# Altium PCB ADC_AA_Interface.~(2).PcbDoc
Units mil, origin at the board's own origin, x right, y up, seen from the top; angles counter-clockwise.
Board outline 2600 x 10000 mil, 6 copper layers (Top Layer, InternalPlane1, MidLayer1, InternalPlane2, InternalPlane3, Bottom Layer); 10 components, 66 nets, 279 pads, 13 vias.
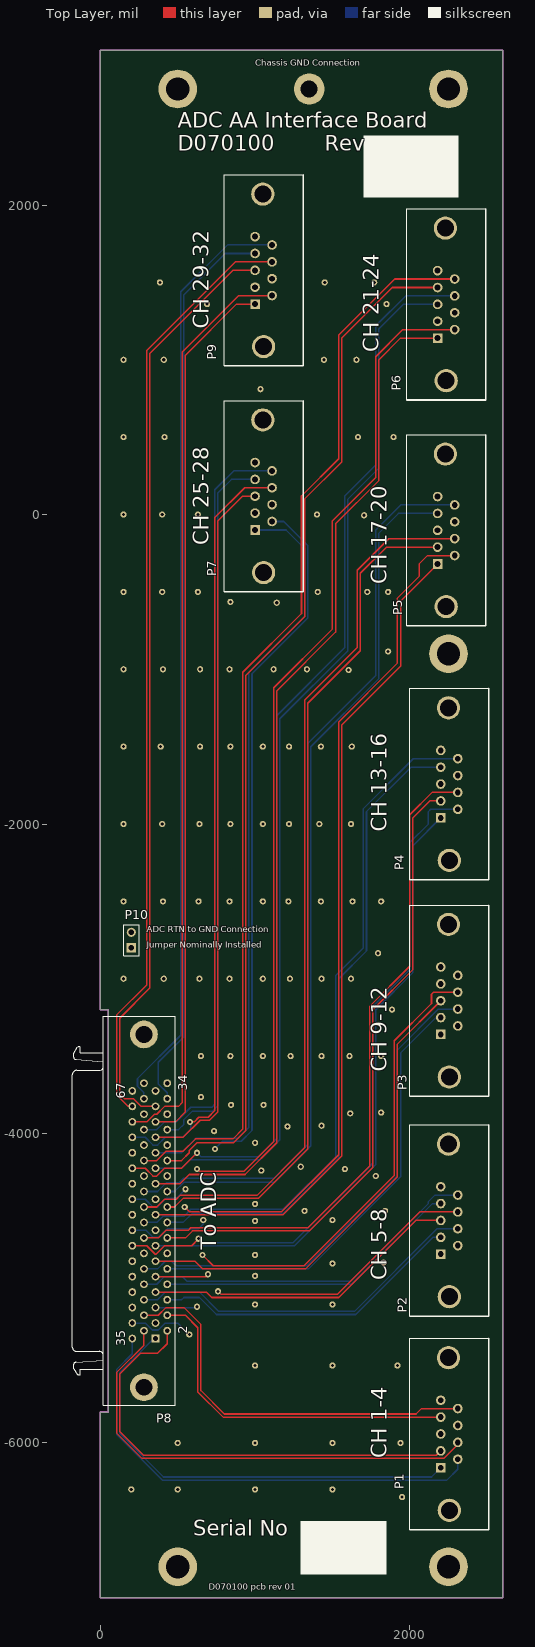
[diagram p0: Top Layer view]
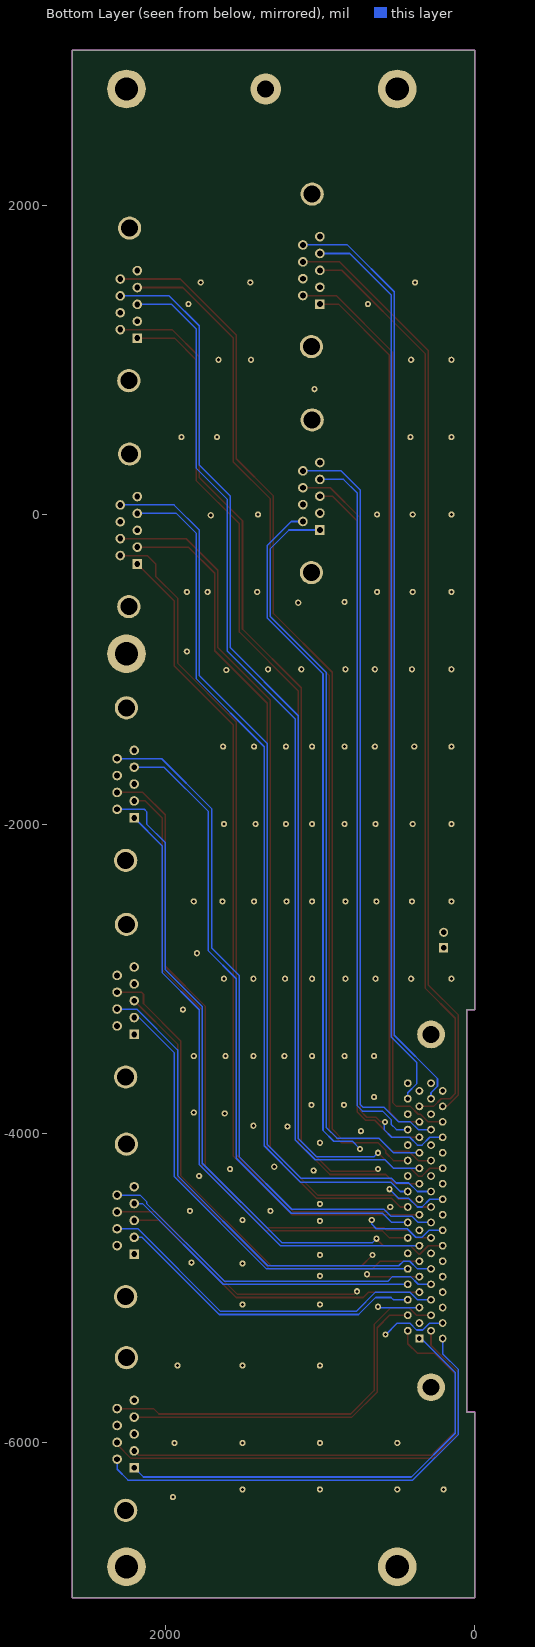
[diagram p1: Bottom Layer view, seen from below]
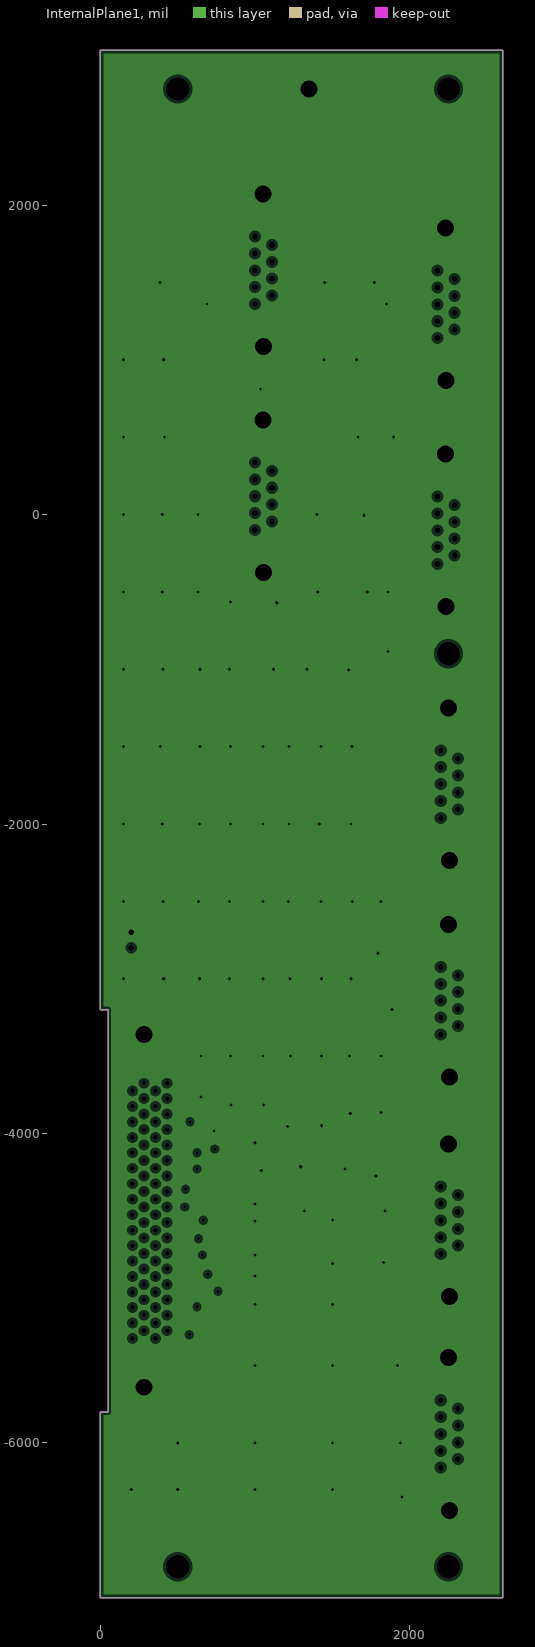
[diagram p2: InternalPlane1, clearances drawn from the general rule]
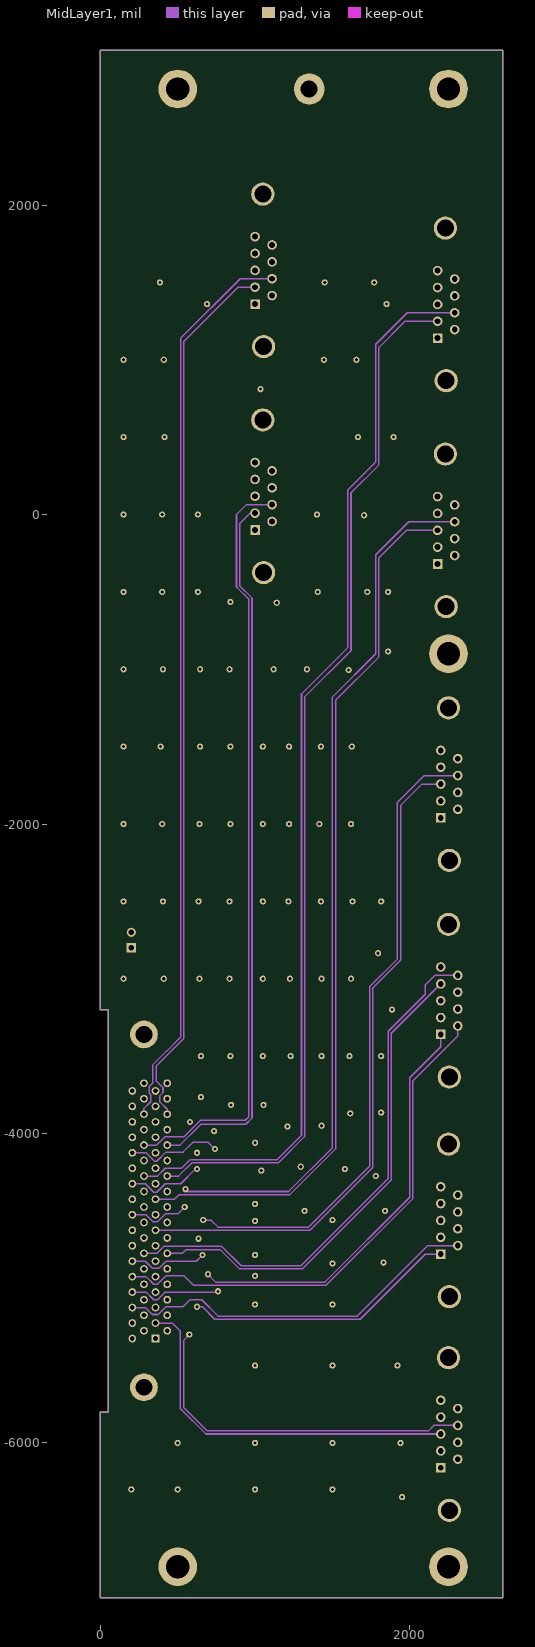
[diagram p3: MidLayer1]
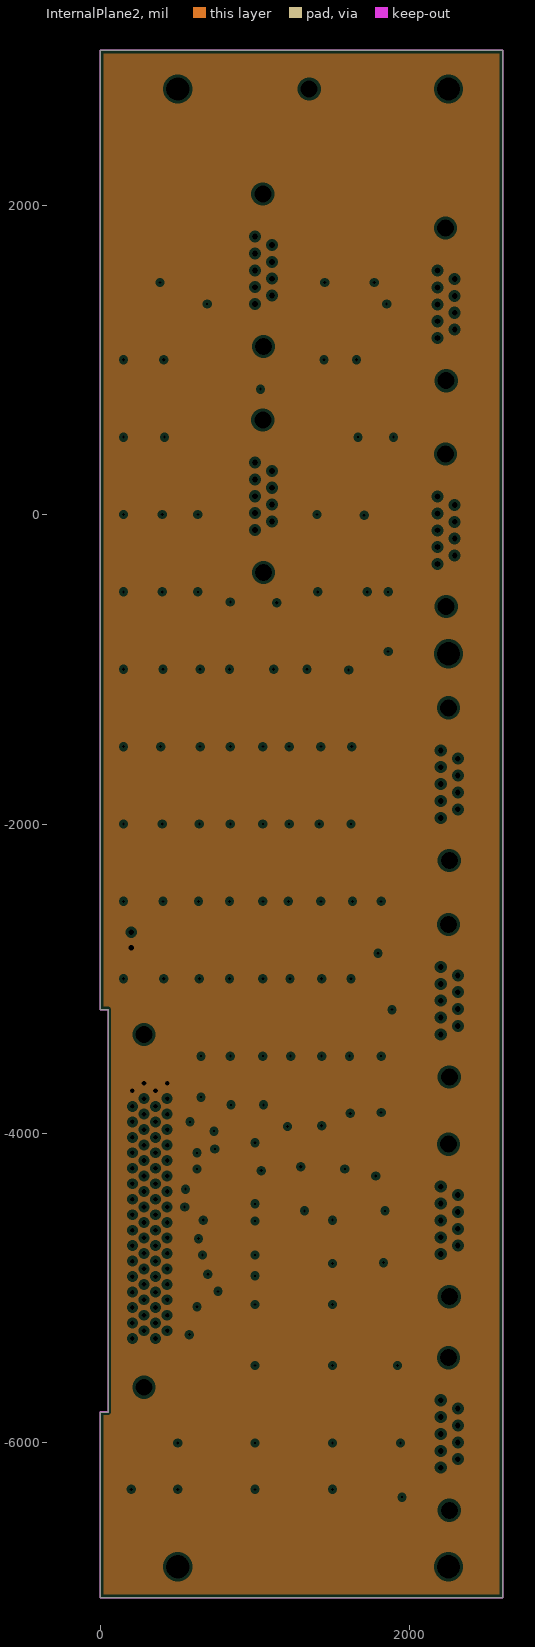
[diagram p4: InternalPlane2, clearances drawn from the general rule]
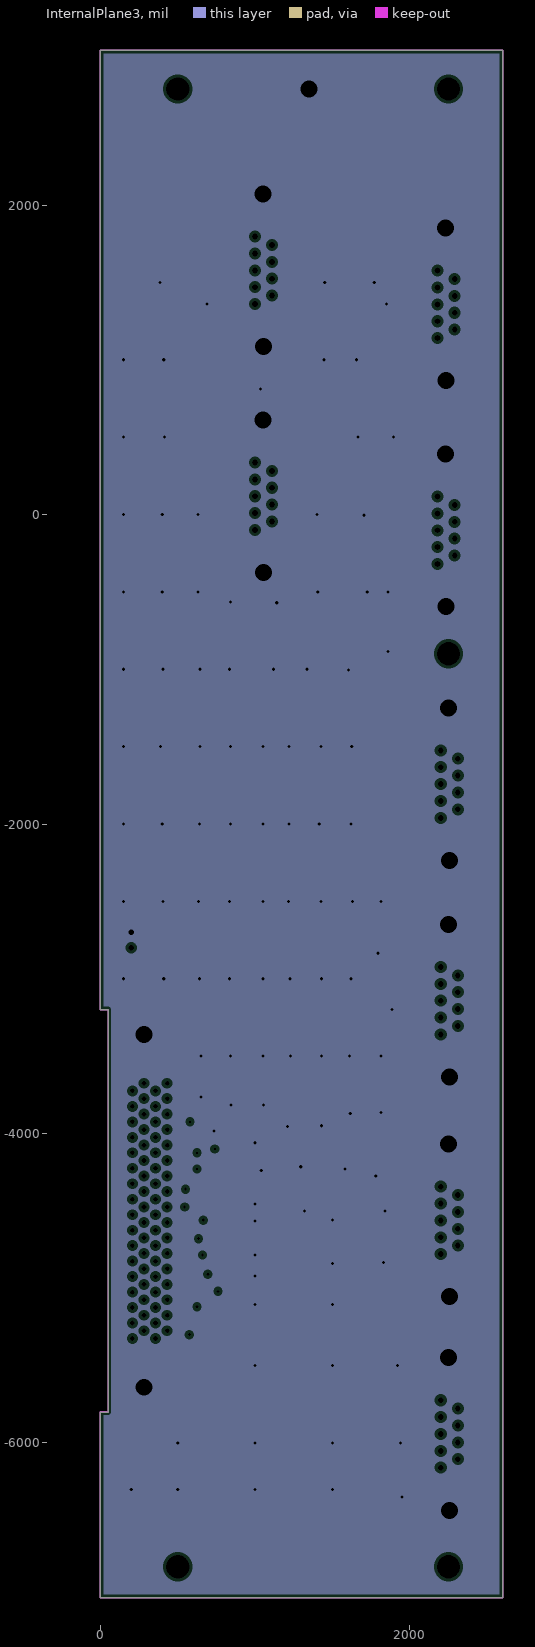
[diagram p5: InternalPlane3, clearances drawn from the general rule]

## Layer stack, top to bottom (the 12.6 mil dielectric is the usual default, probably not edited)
Top Solder: solder mask 0.4, Solder Resist, Dk 3.5
Top Layer: signal copper 1.4
Dielectric1: core 12.6, FR-4, Dk 4.8
InternalPlane1: plane copper 1.4
Dielectric3: prepreg 12.6, FR-4, Dk 4.8
MidLayer1: signal copper 1.4
Dielectric2: core 12.6, FR-4, Dk 4.8
InternalPlane2: plane copper 1.4
Dielectric4: prepreg 12.6, FR-4, Dk 4.8
InternalPlane3: plane copper 1.4
Dielectric5: core 12.6, FR-4, Dk 4.8
Bottom Layer: signal copper 1.4
Bottom Solder: solder mask 0.4, Solder Resist, Dk 3.5

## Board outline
0,-7000 0,-5800 50,-5800 50,-3200 0,-3200 0,3000 2600,3000 2600,-7000

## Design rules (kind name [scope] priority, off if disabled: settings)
Clearance [All] p1: gap=10 ignorepadtopadclearanceinfootprint=FALSE except(0: Arc-Hole Track-Hole SMDPad-Hole THPad-Hole Via-Hole Fill-Hole Poly-Hole Region-Hole Text-Hole)
FabricationTestPointUsage TestPointUsage [All] p1: valid=0 allowmultiple=FALSE
FabricationTestpoint Testpoint [All] p1: side=3 testpointundercomponent=TRUE minsize=40 maxsize=100 preferedsize=60 minholesize=0 maxholesize=40 preferedholesize=32 testpointgrid=1 allowsidetop=TRUE allowsidebottom=TRUE usegrid=TRUE gridtolerance=0.01
HoleSize [All] p1: absolutevalues=TRUE maxlimit=200 minlimit=1 maxpercent=80.000 minpercent=20.000
PlaneClearance [All] p1: clearance=20
PlaneConnect [All] p1: planeconnectstyle=Relief reliefexpansion=20 reliefentries=4 reliefconductorwidth=10 reliefairgap=10
PolygonConnect [All] p1: connectstyle=Relief reliefconductorwidth=10 reliefentries=4 polygonreliefangle="90 Angle" airgapwidth=10
RoutingVias [All] p1: holewidth=20 width=40 viastyle="Through Hole" minholewidth=20 minwidth=40 maxholewidth=28 maxwidth=50
SolderMaskExpansion [All] p1: expansion=4
Width [All] p1: maxlimit=100 minlimit=10 preferedwidth=10
25 further rules are at their usual default settings.

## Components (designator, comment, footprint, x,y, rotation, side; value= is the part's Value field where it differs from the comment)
P1 "5747871-8" DB9/M 2200,-6160 r270 top
P2 "5747871-8" DB9/M 2200,-4780 r270 top
P3 "5747871-8" DB9/M 2200,-3360 r270 top
P4 "5747871-8" DB9/M 2200,-1960 r270 top
P5 "5747871-8" DB9/M 2180,-320 r270 top
P6 "5747871-8" DB9/M 2180,1140 r270 top
P7 "5747871-8" DB9/M 1000,-100 r270 top
P8 "787082-7" 787082-7 20,-4500 r90 top
P9 "5747871-8" DB9/M 1000,1360 r270 top
P10 "Header 2" HDR1X2 200,-2800 r90 top

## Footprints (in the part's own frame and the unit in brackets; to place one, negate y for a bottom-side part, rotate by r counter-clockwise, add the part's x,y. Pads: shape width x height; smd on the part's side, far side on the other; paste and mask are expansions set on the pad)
787082-7 [mm] "Connector; D Subminiature 050 Series; 68 Position; Right Angle"
  rect 1.27x1.27 hole 0.762: 1(-20.955,-8.555)
  round 1.27 hole 0.762: 2(-19.685,-10.46) 3(-18.415,-8.555) 4(-17.145,-10.46) 5(-15.875,-8.555) 6(-14.605,-10.46) 7(-13.335,-8.555) 8(-12.065,-10.46) 9(-10.795,-8.555) 10(-9.525,-10.46) 11(-8.255,-8.555) 12(-6.985,-10.46) 13(-5.715,-8.555) 14(-4.445,-10.46) 15(-3.175,-8.555) 16(-1.905,-10.46) 17(-0.635,-8.555) 18(0.635,-10.46) 19(1.905,-8.555) 20(3.175,-10.46) 21(4.445,-8.555) 22(5.715,-10.46) 23(6.985,-8.555) 24(8.255,-10.46) 25(9.525,-8.555) 26(10.795,-10.46) 27(12.065,-8.555) 28(13.335,-10.46) 29(14.605,-8.555) 30(15.875,-10.46) 31(17.145,-8.555) 32(18.415,-10.46) 33(19.685,-8.555) 34(20.955,-10.46) 35(-20.955,-4.745) 36(-19.685,-6.65) 37(-18.415,-4.745) 38(-17.145,-6.65) 39(-15.875,-4.745) 40(-14.605,-6.65) 41(-13.335,-4.745) 42(-12.065,-6.65) 43(-10.795,-4.745) 44(-9.525,-6.65) 45(-8.255,-4.745) 46(-6.985,-6.65) 47(-5.715,-4.745) 48(-4.445,-6.65) 49(-3.175,-4.745) 50(-1.905,-6.65) 51(-0.635,-4.745) 52(0.635,-6.65) 53(1.905,-4.745) 54(3.175,-6.65) 55(4.445,-4.745) 56(5.715,-6.65) 57(6.985,-4.745) 58(8.255,-6.65) 59(9.525,-4.745) 60(10.795,-6.65) 61(12.065,-4.745) 62(13.335,-6.65) 63(14.605,-4.745) 64(15.875,-6.65) 65(17.145,-4.745) 66(18.415,-6.65) 67(19.685,-4.745) 68(20.955,-6.65)
  round 4.55 hole 2.77: 69(-28.955,-6.65) 70(28.955,-6.65)
  silkscreen extent -31.95,-11.76 31.95,5.11
DB9/M [mil]
  round 150 hole 110: 0(-711,50) 0(275,55)
  rect 62x62 hole 38: 1(0,0)
  round 62 hole 38: 2(-109,0) 3(-218,0) 4(-327,0) 5(-436,0) 6(-55,110) 7(-164,110) 8(-273,110) 9(-382,110)
  silkscreen extent -836,-200 400,310
HDR1X2 [mm] "Connector; Header; 2 Position"
  rect 1.5x1.5 hole 0.9: 1(0,0)
  round 1.5 hole 0.9: 2(2.54,0)
  silkscreen extent -1.27,-1.27 3.81,1.27

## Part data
P1 P2 P3 P4 P5 P6 P7 P9: library part 788754-1, "Plug Assembly, Size 1, 9 Position, Right Angle, 8.08mm Series, Amplimite"
P8: library part "PE50E-080 Connector", "3M Pak 50 plug connector"
P10: "Header, 2-Pin"

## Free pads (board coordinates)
  round 40 hole 20: 0(500,-6000) 1(1000,-6000) 2(1500,-6000) 3(1940,-6000) 4(1000,-5500) 5(1500,-5500) 6(1920,-5500) 7(1000,-4920) 8(1500,-4840) 9(1840,-4500) 10(1000,-5105) 11(1500,-5105) 12(1830,-4835) 13(1000,-4785) 14(1500,-4560) 15(1780,-4275) 16(1815,-3865) 17(1815,-3500) 18(1885,-3200) 19(1000,-4565) 20(1320,-4500) 21(1580,-4230) 22(1615,-3870) 23(1610,-3500) 24(1620,-3000) 25(1795,-2835) 26(1000,-4455) 27(1295,-4215) 28(1040,-4240) 29(1430,-3950) 30(1430,-3500) 31(1430,-3000) 32(1230,-3500) 33(1225,-3000) 34(1210,-3955) 35(1000,-4060) 36(735,-3985) 37(845,-3815) 38(840,-3500) 39(835,-3000) 40(835,-2500) 41(405,-2500) 42(635,-2500) 43(410,-3000) 44(640,-3000) 45(1050,-2500) 46(1215,-2500) 47(1425,-2500) 48(1630,-2500) 49(1815,-2500) 50(650,-3500) 51(650,-3765) 52(1055,-3815) 53(1050,-3500) 54(1050,-3000) 55(400,-2000) 56(640,-2000) 57(840,-2000) 58(1050,-2000) 59(1220,-2000) 60(1415,-2000) 61(1620,-2000) 62(1625,-1500) 63(1425,-1500) 64(1220,-1500) 65(1050,-1500) 66(840,-1500) 67(645,-1500) 68(390,-1500) 69(405,-1000) 70(645,-1000) 71(835,-1000) 72(1120,-1000) 73(1335,-1000) 74(1605,-1005) 75(1860,-885) 76(150,1000) 76(1860,-500) 77(150,500) 77(1725,-500) 78(150,0) 78(400,-500) 79(150,-500) 79(630,-500) 80(150,-1000) 80(840,-565) 81(150,-1500) 81(1140,-570) 82(150,-2000) 82(1405,-500) 83(150,-2500) 83(400,0) 84(150,-3000) 84(630,0) 85(200,-6300) 85(1400,0) 86(500,-6300) 86(1705,-5) 87(1000,-6300) 87(1665,500) 88(415,500) 88(1500,-6300) 89(410,1000) 89(1950,-6350) 90(1035,810) 91(1445,1000) 92(1655,1000) 93(1895,500) 94(1450,1500) 95(1770,1500) 96(385,1500) 97(690,1360) 98(1850,1360)
  round 200 hole 110: 0(1350,2750)
  round 250 hole 150: 0(2250,-6800) 1(2250,2750) 2(500,2750) 3(500,-6800) 4(2250,-900)

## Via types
v1: diameter 40, hole 20, Top Layer to Bottom Layer, 13 vias

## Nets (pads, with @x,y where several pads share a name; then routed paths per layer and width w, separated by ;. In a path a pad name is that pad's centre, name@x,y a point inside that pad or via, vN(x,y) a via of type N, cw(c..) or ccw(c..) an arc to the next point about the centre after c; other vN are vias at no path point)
GND: P1.0 P2.0 P3.0 P4.0 P5.0 P6.0 P7.0 P8.69 P8.70 P9.0 P10.2 pad.0@500,-6000 pad.0@1350,2750 pad.1@1000,-6000 pad.2@1500,-6000 pad.3@1940,-6000 pad.4@1000,-5500 pad.5 pad.6 pad.7 pad.8 pad.9 pad.10 pad.11 pad.12 pad.13 pad.14 pad.15 pad.16 pad.17 pad.18 pad.19 pad.20 pad.21 pad.22 pad.23 pad.24 pad.25 pad.26 pad.27 pad.28 pad.29 pad.30 pad.31 pad.32 pad.33 pad.34 pad.35 pad.36 pad.37 pad.38 pad.39 pad.40 pad.41 pad.42 pad.43 pad.44 pad.45 pad.46 pad.47 pad.48 pad.49 pad.50 pad.51 pad.52 pad.53 pad.54 pad.55 pad.56 pad.57 pad.58 pad.59 pad.60 pad.61 pad.62 pad.63 pad.64 pad.65 pad.66 pad.67 pad.68 pad.69 pad.70 pad.71 pad.72 pad.73 pad.74 pad.75 pad.76 pad.77 pad.78 pad.79 pad.80 pad.81 pad.82 pad.83 pad.84 pad.85 pad.86 pad.87 pad.88 pad.89 pad.90 pad.91 pad.92 pad.93 pad.94 pad.95 pad.96 pad.97 pad.98
OUTPUTN1: P1.6 P8.35 | length 3083.4
  Bottom Layer w10: P8.35 206.81,-5423.19 105,-5525 105,-5945 400,-6240 2240,-6240 2310,-6170 P1.6
OUTPUTN2: P1.7 P8.36 | length 3057.9
  Top Layer w10: P8.36 281.81,-5368.19 105,-5545 105,-5935 270,-6100 2220,-6100 2310,-6010 P1.7
OUTPUTN3: P1.8 P8.37 | length 2769.5
  MidLayer1 w10: v1(575,-5300) 540,-5335 540,-5771.72 690.28,-5922 2120,-5922 2155,-5887 P1.8
  Bottom Layer w10: P8.37 290,-5225 335,-5270 375,-5270 420,-5225 500,-5225 v1(575,-5300)
OUTPUTN4: P1.9 P8.38 | length 2598.3
  Top Layer w10: P8.38 375,-5175 425,-5125 540,-5125 650,-5235 650,-5661.72 801.28,-5813 2040,-5813 2075,-5778 P1.9
OUTPUTN5: P2.6 P8.39 | length 2393.1
  MidLayer1 w10: P8.39 290,-5125 335,-5170 375,-5170 425,-5120 535,-5120 580,-5075 655,-5075 760,-5180 1660,-5180 2115,-4725 P2.6
OUTPUTN6: P2.7 P8.40 | length 2321.9
  Bottom Layer w10: P8.40 370,-5075 420,-5025 640,-5025 765,-5150 1641.72,-5150 2175.72,-4616 P2.7
OUTPUTN7: P2.8 P8.41 | length 2375.7
  Top Layer w10: v1(760,-5020) 780,-5040 1531.72,-5040 2064.72,-4507 P2.8
  MidLayer1 w10: P8.41 295,-5025 345,-5075 370,-5075 420,-5025 755,-5025 v1(760,-5020)
OUTPUTN8: P2.9 P8.42 | length 2298.9
  Bottom Layer w10: P8.42 365,-4975 415,-4925 530,-4925 560,-4955 1616.72,-4955 2120,-4451.72 2120,-4440 2162,-4398 P2.9
OUTPUTN9: P3.6 P8.43 | length 3348.6
  MidLayer1 w10: P8.43 295,-4925 345,-4975 370,-4975 425,-4920 540,-4920 600,-4980 1460,-4980 2020,-4420 2020,-3660 2310,-3370 P3.6
OUTPUTN10: P3.7 P8.44 | length 3224
  Bottom Layer w10: P8.44 370,-4875 420,-4825 460,-4825 490,-4855 1336.72,-4855 1920,-4271.72 1920,-3460 2184,-3196 P3.7
OUTPUTN11: P3.8 P8.45 | length 3464.1
  Top Layer w10: v1(660,-4785) 730,-4855 1316.72,-4855 1900,-4271.72 1900,-3400 2140,-3160 2140,-3100 2153,-3087 P3.8
  MidLayer1 w10: P8.45 290,-4825 335,-4870 380,-4870 425,-4825 620,-4825 v1(660,-4785)
OUTPUTN12: P3.9 P8.46 | length 3468.7
  MidLayer1 w10: P8.46 365,-4775 410,-4730 785,-4730 910,-4855 1296.72,-4855 1860,-4291.72 1860,-3340 2100,-3100 2100,-3040 2162,-2978 P3.9
OUTPUTN13: P4.6 P8.47 | length 4457.4
  Top Layer w10: P8.47 300,-4725 355,-4780 360,-4780 415,-4725 590,-4725 v1(635,-4680)
  Bottom Layer w10: v1(635,-4680) 660,-4705 1246.72,-4705 1760,-4191.72 1760,-3180 2000,-2940 2000,-2120 2120,-2000 2120,-1920 2135,-1905 P4.6
OUTPUTN14: P4.7 P8.48 | length 4399.1
  Top Layer w10: P8.48 375,-4675 425,-4625 570,-4625 585,-4610 1341.72,-4610 1740,-4211.72 1740,-3180 2000,-2920 2000,-1940 2144,-1796 P4.7
OUTPUTN15: P4.8 P8.49 | length 4681.5
  MidLayer1 w10: v1(665,-4560) 715,-4560 760,-4605 1346.72,-4605 1740,-4211.72 1740,-3051.72 1920,-2871.72 1920,-1860 2093,-1687 P4.8
  Bottom Layer w10: P8.49 295,-4625 340,-4670 380,-4670 435,-4615 635,-4615 665,-4585 v1(665,-4560)
OUTPUTN16: P4.9 P8.50 | length 4483.2
  Bottom Layer w10: P8.50 365,-4575 405,-4535 540,-4535 585,-4490 1181.72,-4490 1520,-4151.72 1520,-2980 1700,-2800 1700,-1900 2022,-1578 P4.9
OUTPUTN17: P5.6 P8.51 | length 5841
  Top Layer w10: v1(545,-4475) 575,-4505 1171.72,-4505 1540,-4136.72 1540,-1340 1920,-960 1920,-540 2060,-400 2060,-320 2115,-265 P5.6
  MidLayer1 w10: P8.51 295,-4525 340,-4570 370,-4570 420,-4520 500,-4520 v1(545,-4475)
OUTPUTN18: P5.7 P8.52 | length 5784
  Top Layer w10: P8.52 365,-4475 415,-4425 490,-4425 515,-4400 1011.72,-4400 1320,-4091.72 1320,-1200 1660,-860 1660,-360 1864,-156 P5.7
OUTPUTN19: P5.8 P8.53 | length 6031
  MidLayer1 w10: v1(550,-4360) 565,-4375 1216.72,-4375 1500,-4091.72 1500,-1180 1780,-900 1780,-260 1993,-47 P5.8
  Bottom Layer w10: P8.53 290,-4425 340,-4475 370,-4475 425,-4420 490,-4420 v1(550,-4360)
OUTPUTN20: P5.9 P8.54 | length 5914.9
  Bottom Layer w10: P8.54 370,-4375 425,-4320 506.72,-4320 536.72,-4290 1121.72,-4290 1340,-4071.72 1340,-1480 1780,-1040 1780,-100 1942,62 P5.9
OUTPUTN21: P6.6 P8.55 | length 7012
  Top Layer w10: v1(625,-4230) 640,-4245 926.72,-4245 1120,-4051.72 1120,-1120 1500,-740 1500,-40 1780,240 1780,1020 1955,1195 P6.6
  MidLayer1 w10: P8.55 290,-4325 345,-4380 365,-4380 420,-4325 520,-4325 615,-4230 v1(625,-4230)
OUTPUTN22: P6.7 P8.56 | length 7032.3
  MidLayer1 w10: P8.56 370,-4275 420,-4225 525,-4225 580,-4170 1141.72,-4170 1300,-4011.72 1300,-1160 1600,-860 1600,160 1780,340 1780,1100 1984,1304 P6.7
OUTPUTN23: P6.8 P8.57 | length 7182.1
  Top Layer w10: P8.57 290,-4225 340,-4275 365,-4275 415,-4225 525,-4225 v1(625,-4125)
  Bottom Layer w10: v1(625,-4125) 650,-4150 1021.72,-4150 1140,-4031.72 1140,-1300 1580,-860 1580,120 1780,320 1780,1220 1973,1413 P6.8
OUTPUTN24: P6.9 P8.58 | length 7010.9
  Top Layer w10: P8.58 365,-4175 425,-4115 535,-4115 615,-4035 856.72,-4035 920,-3971.72 920,-1020 1300,-640 1300,120 1540,360 1540,1160 1902,1522 P6.9
OUTPUTN25: P7.6 P8.59 | length 5137.3
  MidLayer1 w10: P8.59 295,-4125 350,-4180 365,-4180 425,-4120 535,-4120 597.5,-4057.5 697.5,-4057.5 v1(740,-4100)
  Bottom Layer w10: v1(740,-4100) 790,-4050 910,-4050 980,-3980 980,-1028.28 1340,-668.28 1340,-200 1185,-45 P7.6
OUTPUTN26: P7.7 P8.60 | length 4935.5
  MidLayer1 w10: P8.60 365,-4075 420,-4020 541.72,-4020 646.72,-3915 936.72,-3915 960,-3891.72 960,-548.28 880,-468.28 880,0 944,64 P7.7
OUTPUTN27: P7.8 P8.61 | length 4964.4
  Top Layer w10: v1(580,-3925) 606.72,-3925 636.72,-3895 696.72,-3895 740,-3851.72 740,-20 933,173 P7.8
  Bottom Layer w10: P8.61 290,-4025 340,-4075 370,-4075 420,-4025 535,-4025 585,-3975 585,-3930 v1(580,-3925)
OUTPUTN28: P7.9 P8.62 | length 4918.1
  Bottom Layer w10: P8.62 365,-3975 415,-3925 490,-3925 585,-3830 721.72,-3830 740,-3811.72 740,160 862,282 P7.9
OUTPUTN29: P8.63 P9.6 | length 5956.2
  Top Layer w10: P8.63 300,-3925 350,-3875 365,-3875 415,-3825 505,-3825 530,-3800 530,1050 895,1415 P9.6
OUTPUTN30: P8.64 P9.7 | length 5872
  MidLayer1 w10: P8.64 281.81,-3838.19 325,-3795 325,-3749.25 315,-3739.25 315,-3697.33 340,-3672.33 340,-3555 425,-3470 426.72,-3470 520,-3376.72 520,1140 904,1524 P9.7
OUTPUTN31: P8.65 P9.8 | length 6071
  Top Layer w10: P8.65 180,-3825 105,-3750 105,-3235 300,-3040 300,1060 873,1633 P9.8
OUTPUTN32: P8.66 P9.9 | length 6063.4
  Bottom Layer w10: P8.66 281.81,-3736.81 240,-3695 240,-3645 520,-3365 520,1440 822,1742 P9.9
OUTPUTP1: P1.1 P8.1 | length 2931.8
  Bottom Layer w10: P8.1 345,-5325 125,-5545 125,-5936.72 408.28,-6220 2140,-6220 P1.1
OUTPUTP2: P1.2 P8.2 | length 2993.7
  Top Layer w10: P8.2 431.81,-5358.19 370,-5420 260,-5420 125,-5555 125,-5926.72 278.28,-6080 2171,-6080 P1.2
OUTPUTP3: P1.3 P8.3 | length 2433.1
  MidLayer1 w10: P8.3 465,-5225 515,-5275 515,-5775 682,-5942 P1.3
OUTPUTP4: P1.4 P8.4 | length 2283.8
  Top Layer w10: P8.4 550,-5175 630,-5255 630,-5670 793,-5833 P1.4
OUTPUTP5: P2.1 P8.5 | length 2055.3
  MidLayer1 w10: v1(625,-5120) 660,-5120 740,-5200 1680,-5200 2100,-4780 P2.1
  Bottom Layer w10: P8.5 625,-5125 v1(625,-5120)
OUTPUTP6: P2.2 P8.6 | length 2026.7
  Bottom Layer w10: P8.6 525,-5075 540,-5060 640,-5060 750,-5170 1650,-5170 2149,-4671 P2.2
OUTPUTP7: P2.3 P8.7 | length 2064
  Top Layer w10: P8.7 685,-5025 720,-5060 1540,-5060 2038,-4562 P2.3
OUTPUTP8: P2.4 P8.8 | length 1984.4
  Bottom Layer w10: P8.8 1625,-4975 2147,-4453 P2.4
OUTPUTP9: P3.1 P8.9 | length 3040.6
  Top Layer w10: P8.9 695,-4925 v1(695,-4910)
  MidLayer1 w10: v1(695,-4910) 745,-4960 1451.72,-4960 2000,-4411.72 2000,-3640 2200,-3440 P3.1
OUTPUTP10: P3.2 P8.10 | length 2909.5
  Bottom Layer w10: P8.10 1345,-4875 1940,-4280 1940,-3480 2169,-3251 P3.2
OUTPUTP11: P3.3 P8.11 | length 3084.3
  Top Layer w10: P8.11 611.36,-4825 661.36,-4875 1325,-4875 1920,-4280 1920,-3422 P3.3
OUTPUTP12: P3.4 P8.12 | length 3148
  MidLayer1 w10: P8.12 530,-4775 555,-4750 773.75,-4750 898.75,-4875 1305,-4875 1880,-4300 1880,-3353 P3.4
OUTPUTP13: P4.1 P8.13 | length 4054.6
  Bottom Layer w10: P8.13 1255,-4725 1780,-4200 1780,-3200 2020,-2960 2020,-2140 P4.1
OUTPUTP14: P4.2 P8.14 | length 4109.5
  Top Layer w10: P8.14 550,-4675 595,-4630 1350,-4630 1760,-4220 1760,-3200 2020,-2940 2020,-1960 2129,-1851 P4.2
OUTPUTP15: P4.3 P8.15 | length 4302.7
  MidLayer1 w10: P8.15 1355,-4625 1760,-4220 1760,-3060 1940,-2880 1940,-1880 2078,-1742 P4.3
OUTPUTP16: P4.4 P8.16 | length 4193.5
  Bottom Layer w10: P8.16 535,-4575 595,-4515 1185,-4515 1540,-4160 1540,-3000 1720,-2820 1720,-1920 2007,-1633 P4.4
OUTPUTP17: P5.1 P8.17 | length 5442.4
  Top Layer w10: P8.17 1180,-4525 1560,-4145 1560,-1360 1940,-980 1940,-560 P5.1
OUTPUTP18: P5.2 P8.18 | length 5494.4
  Top Layer w10: P8.18 480,-4475 535,-4420 1020,-4420 1340,-4100 1340,-1220 1680,-880 1680,-380 1849,-211 P5.2
OUTPUTP19: P5.3 P8.19 | length 5687.5
  MidLayer1 w10: P8.19 480,-4425 510,-4395 1225,-4395 1520,-4100 1520,-1200 1800,-920 1800,-280 1978,-102 P5.3
OUTPUTP20: P5.4 P8.20 | length 5625.2
  Bottom Layer w10: P8.20 480,-4375 540,-4315 1125,-4315 1360,-4080 1360,-1500 1800,-1060 1800,-120 1927,7 P5.4
OUTPUTP21: P6.1 P8.21 | length 6664.3
  Top Layer w10: P8.21 515,-4325 575,-4265 935,-4265 1140,-4060 1140,-1140 1520,-760 1520,-60 1800,220 1800,1000 1940,1140 P6.1
OUTPUTP22: P6.2 P8.22 | length 6742.6
  MidLayer1 w10: P8.22 505,-4275 590,-4190 1150,-4190 1320,-4020 1320,-1180 1620,-880 1620,140 1800,320 1800,1080 1969,1249 P6.2
OUTPUTP23: P6.3 P8.23 | length 6830.4
  Bottom Layer w10: P8.23 525,-4225 580,-4170 1030,-4170 1160,-4040 1160,-1320 1600,-880 1600,100 1800,300 1800,1200 1958,1358 P6.3
OUTPUTP24: P6.4 P8.24 | length 6730
  Top Layer w10: P8.24 525,-4175 575,-4125 575,-4110 625,-4060 860,-4060 940,-3980 940,-1040 1320,-660 1320,100 1560,340 1560,1140 1887,1467 P6.4
OUTPUTP25: P7.1 P8.25 | length 4930.4
  Bottom Layer w10: P8.25 525,-4125 620,-4030 890,-4030 960,-3960 960,-1020 1320,-660 1320,-220 1200,-100 P7.1
OUTPUTP26: P7.2 P8.26 | length 4622.4
  MidLayer1 w10: P8.26 515,-4075 650,-3940 940,-3940 980,-3900 980,-540 900,-460 900,-60 969,9 P7.2
OUTPUTP27: P7.3 P8.27 | length 4597
  Top Layer w10: P8.27 535,-4025 645,-3915 705,-3915 760,-3860 760,-40 918,118 P7.3
OUTPUTP28: P7.4 P8.28 | length 4646
  Bottom Layer w10: P8.28 505,-3975 540,-3940 540,-3910 595,-3855 725,-3855 760,-3820 760,140 847,227 P7.4
OUTPUTP29: P8.29 P9.1 | length 5696.8
  Top Layer w10: P8.29 485,-3925 550,-3860 550,1030 880,1360 P9.1
OUTPUTP30: P8.30 P9.2 | length 5720.4
  MidLayer1 w10: P8.30 431.81,-3843.43 385,-3796.62 385,-3755 405,-3735 405,-3705 360,-3660 360,-3565 540,-3385 540,1120 889,1469 P9.2
OUTPUTP31: P8.31 P9.3 | length 6031.6
  Top Layer w10: P8.31 265,-3825 215,-3775 158.28,-3775 125,-3741.72 125,-3255 320,-3060 320,1040 858,1578 P9.3
OUTPUTP32: P8.32 P9.4 | length 5857.5
  Bottom Layer w10: P8.32 431.81,-3736.81 375,-3680 375,-3540 540,-3375 540,1420 807,1687 P9.4
RTN: P8.33 P8.34 P8.67 P8.68 P10.1
pads on no net: P1.5 P2.5 P3.5 P4.5 P5.5 P6.5 P7.5 P9.5

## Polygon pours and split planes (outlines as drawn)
GND on InternalPlane1 (split plane): 2579.9,-6979.9 20.1,-6979.9 20.1,-5820.1 50,-5820.1 53.92,-5819.71 57.69,-5818.57 61.17,-5816.71 64.21,-5814.21 66.71,-5811.17 68.57,-5807.69 69.71,-5803.92 70.1,-5800 70.1,-3200 69.71,-3196.08 68.57,-3192.31 66.71,-3188.83 64.21,-3185.79 61.17,-3183.29 57.69,-3181.43 53.92,-3180.29 50,-3179.9 20.1,-3179.9 20.1,2979.9 2579.9,2979.9
RTN on InternalPlane2 (split plane): 2579.9,-6979.9 20.1,-6979.9 20.1,-5820.1 50,-5820.1 53.92,-5819.71 57.69,-5818.57 61.17,-5816.71 64.21,-5814.21 66.71,-5811.17 68.57,-5807.69 69.71,-5803.92 70.1,-5800 70.1,-3200 69.71,-3196.08 68.57,-3192.31 66.71,-3188.83 64.21,-3185.79 61.17,-3183.29 57.69,-3181.43 53.92,-3180.29 50,-3179.9 20.1,-3179.9 20.1,2979.9 2579.9,2979.9
GND on InternalPlane3 (split plane): 2579.9,-6979.9 20.1,-6979.9 20.1,-5820.1 50,-5820.1 53.92,-5819.71 57.69,-5818.57 61.17,-5816.71 64.21,-5814.21 66.71,-5811.17 68.57,-5807.69 69.71,-5803.92 70.1,-5800 70.1,-3200 69.71,-3196.08 68.57,-3192.31 66.71,-3188.83 64.21,-3185.79 61.17,-3183.29 57.69,-3181.43 53.92,-3180.29 50,-3179.9 20.1,-3179.9 20.1,2979.9 2579.9,2979.9

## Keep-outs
Keep-Out Layer:
  the board outline again, w10

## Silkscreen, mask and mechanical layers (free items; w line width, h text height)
Top Overlay:
  rectangle: 1295,-6850 1850,-6505
  rectangle: 1700,2050 2315,2450
  text "Chassis GND Connection" at 1000,2900 h40
  text "ADC AA Interface Board" at 500,2500 h100
  text "D070100" at 500,2350 h100
  text "Rev" at 1450,2350 h100
  text "CH 29-32" at 700,1200 h100 r90
  text "CH 21-24" at 1800,1050 h100 r90
  text "CH 25-28" at 700,-200 h100 r90
  text "CH 17-20" at 1850,-450 h100 r90
  text "CH 13-16" at 1850,-2050 h100 r90
  text "ADC RTN to GND Connection" at 300,-2700 h40
  text "Jumper Nominally Installed" at 300,-2800 h40
  text "CH 9-12" at 1850,-3600 h100 r90
  text "To ADC" at 750,-4750 h100 r90
  text "CH 5-8" at 1850,-4950 h100 r90
  text "CH 1-4" at 1850,-6100 h100 r90
  text "Serial No" at 600,-6600 h100
  text "D070100 pcb rev 01" at 700,-6950 h40
Mechanical 1:
  lines w10: 0,-7000 0,-5800 50,-5800 50,-4500 50,-3200 0,-3200 0,3000 2600,3000 2600,-7000 0,-7000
